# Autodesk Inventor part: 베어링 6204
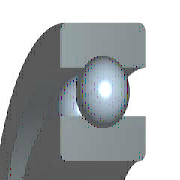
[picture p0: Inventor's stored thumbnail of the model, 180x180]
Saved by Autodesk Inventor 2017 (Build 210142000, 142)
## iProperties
Created: 2012-02
Part Number: 베어링 6204
Material: 강철, 연강
Description: 깊은 그루브 볼 베어링
Document SubType Name: Modeling
Standard: KS B 2023
Designer: mduedu
Standards Organization: KS
Language: ko-KR
Size Designation: 6204 - 20 x 47 x 14
Categories: <MemberInstance><Categories><Category DisplayName="샤프트 부품" InternalName="7f7aeb1f-a693-4053-b835-cee3144e0d98" Mnemonic="SHFT"><Category DisplayName="베어링" Inter
Density: 1 g/cm^3
Appearance: 노란색
IsCustomPart: 1
Author: mduedu
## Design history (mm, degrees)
sketch "스케치" dims "d0" = 7.02 (= -0.26 x WD + 0.26 x BD)
  geometry: L1 (3.49, 16.75)-(10.51, 16.75); L2 (7, 16.75)-(7, 13.24); L3 (7, 16.75)-(7, 20.26); L4 (4.392, 14.401)-(0, 14.401); L5 (0, 10)-(14, 10); L6 (4.392, 19.099)-(0, 19.099); L7 (0, 23.5)-(14, 23.5); L8 (14, 10)-(14, 14.401); L9 (9.608, 14.401)-(14, 14.401); L10 (9.608, 19.099)-(14, 19.099); L11 (14, 23.5)-(14, 19.099); L12 (-1.4, 0)-(8.4, 0) reference; L13 (0, -0.3)-(0, 5.3) reference
  constraints: 22 end point, 4 point on line, 2 collinear, 2 perpendicular, 2 symmetric about line, 1 midpoint, 1 parallel, 14 other
  dimensions: "d9" = 20 diameter of L5 L12 (= WD); "d11" = 47 diameter of L7 L12 (= BD); "d12" = 14 distance between parallel lines of L8 L13 (= KB); "d13" = 28.802 diameter of L9 L12 (= 0.326 x BD + 0.674 x WD)
revolve "본체" stored, may be unused: angle "d6" = 90 deg
revolve "볼" stored, may be unused: angle "d7" = 90 deg
pattern_circular "IDS_ARRAYBALL[SIMPL:T]" dims angle "d3" = 360 deg
body "Solid1"
fillet "모깎기1" dims "d1" = 1 (= KRS)
other parameters: "WD" = 20 [user parameter; used in 5 equation terms], "BD" = 47 [user parameter; used in 5 equation terms], "KB" = 14 [user parameter; used in 1 equation term], "KRS" = 1 [user parameter; used in 1 equation term], "d4" = 0, "d5" = 0, "d8" = 0, "d14" = 0, "d15" = 0, "BBA" = 0 [user parameter], "BC0" = 6550000 [user parameter], "BC" = 1.27e+07 [user parameter], "BR" = 23.5 (= 0.5 x BD) [user parameter]
